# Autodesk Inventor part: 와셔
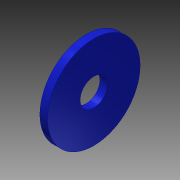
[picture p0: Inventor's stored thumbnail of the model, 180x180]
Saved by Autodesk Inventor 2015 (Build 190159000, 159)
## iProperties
Created: 2015-12
Part Number: 와셔
Material: 스테인리스강
Document SubType Name: Modeling
Designer: mduedu
Density: 8.08 g/cm^3
Mass: 6.77437 g
Surface Area: 10.3005 cm^2
Volume: 0.838413 cm^3
Appearance: 파란색 - 벽 페인트 - 광택
Author: mduedu
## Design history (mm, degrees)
sketch "스케치1"
  geometry: C1 r 2.75 at (0, 0); C2 r 11 at (0, 0); 1 further point
  constraints: 2 centre point, 2 coincident
  dimensions: "d0" = 5.5 diameter of C1; "d1" = 22 diameter of C2
extrude "돌출1" new body sketch "스케치1" stored distance "d2" = 2; taper "d3" = 0 deg
node "솔리드1"
